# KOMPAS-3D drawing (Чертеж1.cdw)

Views: Вид 1, Вид 2
Referenced files in C:\Program Files\ASCON\KOMPAS-3D V16\Templates\: Констр. чертеж А3 гориз. перв. лист.cdt
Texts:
  цуфв
  Стили документа
  Констр. чертеж А3 гориз. перв. лист.cdt
Dimensions and other numbers on the sheet: 9; 8; 7; 6; 5; 4; 3; 2; 1; 1:1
